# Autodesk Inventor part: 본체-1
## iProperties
Created: 2015-05
Part Number: 본체-1
Material: 알루미늄-6061
Document SubType Name: Modeling
Designer: Win7
Mass: 1082.64 g
Surface Area: 1038.64 cm^2
Volume: 399.496 cm^3
Density: 2.71 g/cm^3
Author: Win7
